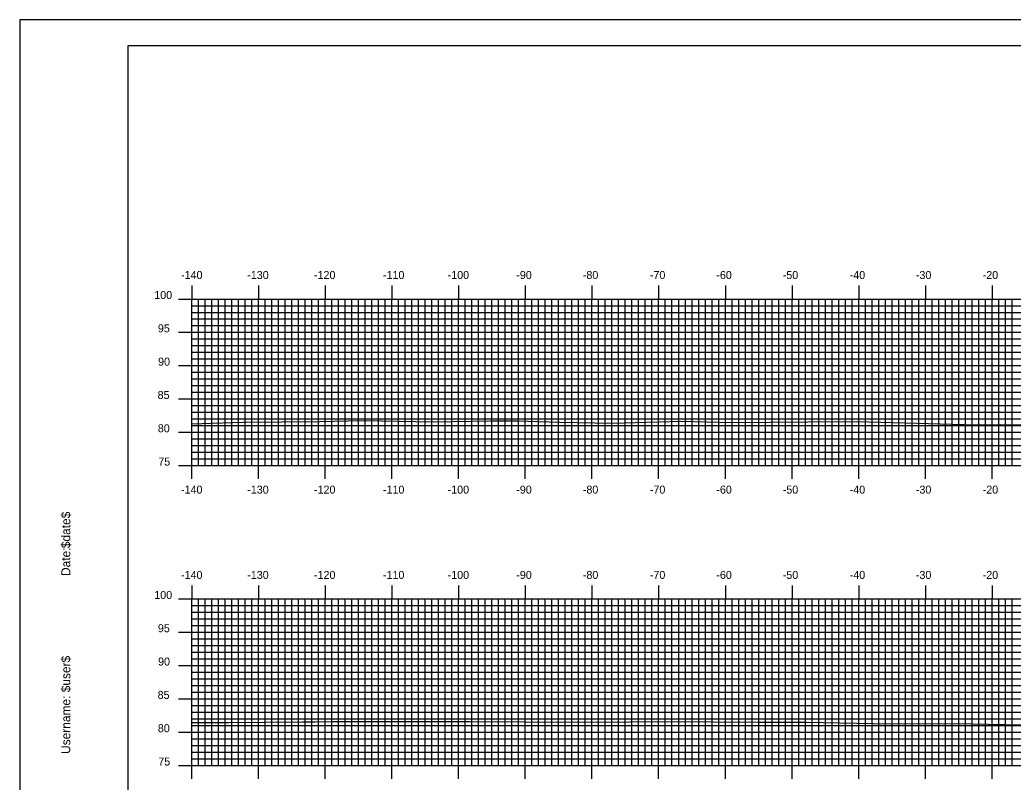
# Model space of a CAD drawing. Extents: x 856323 to 856666, y 364765 to 364985.
# Drawn here: x 856323 to 856471.9, y 364870.8 to 364985.2 of the extents above; entities that cross this region are included whole.
import ezdxf

# ---------------------------------------------------------------- set-up
doc = ezdxf.new("R2010")
doc.units = 0
for name, color, linetype in [('BORDER', 7, 'Continuous'), ('H_V ANNOTATION', 7, 'Continuous'), ('MAJOR', 7, 'Continuous'), ('MINOR', 7, 'Continuous'), ('PLOT BOUNDARY', 7, 'Continuous'), ('S_Roadway_Centerline', 7, 'Continuous')]:
    doc.layers.add(name, color=color, linetype=linetype)

msp = doc.modelspace()

# ---------------------------------------------------------------- linework, layer by layer
at = {"layer": 'BORDER'}
msp.add_lwpolyline([(856339.17, 364771.3), (856659.17, 364771.3), (856659.17, 364981.3), (856339.17, 364981.3)], close=True, dxfattribs=at)
at = {"layer": 'MAJOR'}
for p, q in [((856348.77, 364945.31), (856348.77, 364943.3)), ((856358.77, 364945.31), (856358.77, 364943.3)), ((856368.77, 364945.31), (856368.77, 364943.3)), ((856378.77, 364945.31), (856378.77, 364943.3)), ((856388.77, 364945.31), (856388.77, 364943.3)), ((856398.77, 364945.31), (856398.77, 364943.3)), ((856408.77, 364945.31), (856408.77, 364943.3)), ((856418.77, 364945.31), (856418.77, 364943.3)), ((856428.77, 364945.31), (856428.77, 364943.3)), ((856438.77, 364945.31), (856438.77, 364943.3)), ((856448.77, 364945.31), (856448.77, 364943.3)), ((856458.77, 364945.31), (856458.77, 364943.3)), ((856468.77, 364945.31), (856468.77, 364943.3)), ((856346.76, 364943.3), (856348.77, 364943.3)), ((856348.77, 364943.3), (856628.77, 364943.3)), ((856348.77, 364918.3), (856348.77, 364943.3)), ((856348.77, 364918.3), (856348.77, 364943.3)), ((856348.77, 364943.3), (856628.77, 364943.3)), ((856358.77, 364918.3), (856358.77, 364943.3)), ((856368.77, 364918.3), (856368.77, 364943.3)), ((856378.77, 364918.3), (856378.77, 364943.3)), ((856388.77, 364918.3), (856388.77, 364943.3)), ((856398.77, 364918.3), (856398.77, 364943.3)), ((856408.77, 364918.3), (856408.77, 364943.3)), ((856418.77, 364918.3), (856418.77, 364943.3)), ((856428.77, 364918.3), (856428.77, 364943.3)), ((856438.77, 364918.3), (856438.77, 364943.3)), ((856448.77, 364918.3), (856448.77, 364943.3)), ((856458.77, 364918.3), (856458.77, 364943.3)), ((856468.77, 364918.3), (856468.77, 364943.3)), ((856346.76, 364938.3), (856348.77, 364938.3)), ((856348.77, 364938.3), (856628.77, 364938.3)), ((856346.76, 364933.3), (856348.77, 364933.3)), ((856348.77, 364933.3), (856628.77, 364933.3)), ((856346.76, 364928.3), (856348.77, 364928.3)), ((856348.77, 364928.3), (856628.77, 364928.3)), ((856346.76, 364923.3), (856348.77, 364923.3)), ((856348.77, 364923.3), (856628.77, 364923.3)), ((856346.76, 364918.3), (856348.77, 364918.3)), ((856348.77, 364918.3), (856628.77, 364918.3)), ((856348.77, 364918.3), (856628.77, 364918.3)), ((856348.77, 364916.3), (856348.77, 364918.3)), ((856358.77, 364916.3), (856358.77, 364918.3)), ((856368.77, 364916.3), (856368.77, 364918.3)), ((856378.77, 364916.3), (856378.77, 364918.3)), ((856388.77, 364916.3), (856388.77, 364918.3)), ((856398.77, 364916.3), (856398.77, 364918.3)), ((856408.77, 364916.3), (856408.77, 364918.3)), ((856418.77, 364916.3), (856418.77, 364918.3)), ((856428.77, 364916.3), (856428.77, 364918.3)), ((856438.77, 364916.3), (856438.77, 364918.3)), ((856448.77, 364916.3), (856448.77, 364918.3)), ((856458.77, 364916.3), (856458.77, 364918.3)), ((856468.77, 364916.3), (856468.77, 364918.3)), ((856348.77, 364900.31), (856348.77, 364898.3)), ((856358.77, 364900.31), (856358.77, 364898.3)), ((856368.77, 364900.31), (856368.77, 364898.3)), ((856378.77, 364900.31), (856378.77, 364898.3)), ((856388.77, 364900.31), (856388.77, 364898.3)), ((856398.77, 364900.31), (856398.77, 364898.3)), ((856408.77, 364900.31), (856408.77, 364898.3)), ((856418.77, 364900.31), (856418.77, 364898.3)), ((856428.77, 364900.31), (856428.77, 364898.3)), ((856438.77, 364900.31), (856438.77, 364898.3)), ((856448.77, 364900.31), (856448.77, 364898.3)), ((856458.77, 364900.31), (856458.77, 364898.3)), ((856468.77, 364900.31), (856468.77, 364898.3)), ((856346.76, 364898.3), (856348.77, 364898.3)), ((856348.77, 364898.3), (856628.77, 364898.3)), ((856348.77, 364873.3), (856348.77, 364898.3)), ((856348.77, 364873.3), (856348.77, 364898.3)), ((856348.77, 364898.3), (856628.77, 364898.3)), ((856358.77, 364873.3), (856358.77, 364898.3)), ((856368.77, 364873.3), (856368.77, 364898.3)), ((856378.77, 364873.3), (856378.77, 364898.3)), ((856388.77, 364873.3), (856388.77, 364898.3)), ((856398.77, 364873.3), (856398.77, 364898.3)), ((856408.77, 364873.3), (856408.77, 364898.3)), ((856418.77, 364873.3), (856418.77, 364898.3)), ((856428.77, 364873.3), (856428.77, 364898.3)), ((856438.77, 364873.3), (856438.77, 364898.3)), ((856448.77, 364873.3), (856448.77, 364898.3)), ((856458.77, 364873.3), (856458.77, 364898.3)), ((856468.77, 364873.3), (856468.77, 364898.3)), ((856346.76, 364893.3), (856348.77, 364893.3)), ((856348.77, 364893.3), (856628.77, 364893.3)), ((856346.76, 364888.3), (856348.77, 364888.3)), ((856348.77, 364888.3), (856628.77, 364888.3)), ((856346.76, 364883.3), (856348.77, 364883.3)), ((856348.77, 364883.3), (856628.77, 364883.3)), ((856346.76, 364878.3), (856348.77, 364878.3)), ((856348.77, 364878.3), (856628.77, 364878.3)), ((856346.76, 364873.3), (856348.77, 364873.3)), ((856348.77, 364873.3), (856628.77, 364873.3)), ((856348.77, 364873.3), (856628.77, 364873.3)), ((856348.77, 364871.3), (856348.77, 364873.3)), ((856358.77, 364871.3), (856358.77, 364873.3)), ((856368.77, 364871.3), (856368.77, 364873.3)), ((856378.77, 364871.3), (856378.77, 364873.3)), ((856388.77, 364871.3), (856388.77, 364873.3)), ((856398.77, 364871.3), (856398.77, 364873.3)), ((856408.77, 364871.3), (856408.77, 364873.3)), ((856418.77, 364871.3), (856418.77, 364873.3)), ((856428.77, 364871.3), (856428.77, 364873.3)), ((856438.77, 364871.3), (856438.77, 364873.3)), ((856448.77, 364871.3), (856448.77, 364873.3)), ((856458.77, 364871.3), (856458.77, 364873.3)), ((856468.77, 364871.3), (856468.77, 364873.3))]:
    msp.add_line(p, q, dxfattribs=at)
at = {"layer": 'MINOR'}
for p, q in [((856349.77, 364918.3), (856349.77, 364943.3)), ((856350.77, 364918.3), (856350.77, 364943.3)), ((856351.77, 364918.3), (856351.77, 364943.3)), ((856352.77, 364918.3), (856352.77, 364943.3)), ((856353.77, 364918.3), (856353.77, 364943.3)), ((856354.77, 364918.3), (856354.77, 364943.3)), ((856355.77, 364918.3), (856355.77, 364943.3)), ((856356.77, 364918.3), (856356.77, 364943.3)), ((856357.77, 364918.3), (856357.77, 364943.3)), ((856359.77, 364918.3), (856359.77, 364943.3)), ((856360.77, 364918.3), (856360.77, 364943.3)), ((856361.77, 364918.3), (856361.77, 364943.3)), ((856362.77, 364918.3), (856362.77, 364943.3)), ((856363.77, 364918.3), (856363.77, 364943.3)), ((856364.77, 364918.3), (856364.77, 364943.3)), ((856365.77, 364918.3), (856365.77, 364943.3)), ((856366.77, 364918.3), (856366.77, 364943.3)), ((856367.77, 364918.3), (856367.77, 364943.3)), ((856369.77, 364918.3), (856369.77, 364943.3)), ((856370.77, 364918.3), (856370.77, 364943.3)), ((856371.77, 364918.3), (856371.77, 364943.3)), ((856372.77, 364918.3), (856372.77, 364943.3)), ((856373.77, 364918.3), (856373.77, 364943.3)), ((856374.77, 364918.3), (856374.77, 364943.3)), ((856375.77, 364918.3), (856375.77, 364943.3)), ((856376.77, 364918.3), (856376.77, 364943.3)), ((856377.77, 364918.3), (856377.77, 364943.3)), ((856379.77, 364918.3), (856379.77, 364943.3)), ((856380.77, 364918.3), (856380.77, 364943.3)), ((856381.77, 364918.3), (856381.77, 364943.3)), ((856382.77, 364918.3), (856382.77, 364943.3)), ((856383.77, 364918.3), (856383.77, 364943.3)), ((856384.77, 364918.3), (856384.77, 364943.3)), ((856385.77, 364918.3), (856385.77, 364943.3)), ((856386.77, 364918.3), (856386.77, 364943.3)), ((856387.77, 364918.3), (856387.77, 364943.3)), ((856389.77, 364918.3), (856389.77, 364943.3)), ((856390.77, 364918.3), (856390.77, 364943.3)), ((856391.77, 364918.3), (856391.77, 364943.3)), ((856392.77, 364918.3), (856392.77, 364943.3)), ((856393.77, 364918.3), (856393.77, 364943.3)), ((856394.77, 364918.3), (856394.77, 364943.3)), ((856395.77, 364918.3), (856395.77, 364943.3)), ((856396.77, 364918.3), (856396.77, 364943.3)), ((856397.77, 364918.3), (856397.77, 364943.3)), ((856399.77, 364918.3), (856399.77, 364943.3)), ((856400.77, 364918.3), (856400.77, 364943.3)), ((856401.77, 364918.3), (856401.77, 364943.3)), ((856402.77, 364918.3), (856402.77, 364943.3)), ((856403.77, 364918.3), (856403.77, 364943.3)), ((856404.77, 364918.3), (856404.77, 364943.3)), ((856405.77, 364918.3), (856405.77, 364943.3)), ((856406.77, 364918.3), (856406.77, 364943.3)), ((856407.77, 364918.3), (856407.77, 364943.3)), ((856409.77, 364918.3), (856409.77, 364943.3)), ((856410.77, 364918.3), (856410.77, 364943.3)), ((856411.77, 364918.3), (856411.77, 364943.3)), ((856412.77, 364918.3), (856412.77, 364943.3)), ((856413.77, 364918.3), (856413.77, 364943.3)), ((856414.77, 364918.3), (856414.77, 364943.3)), ((856415.77, 364918.3), (856415.77, 364943.3)), ((856416.77, 364918.3), (856416.77, 364943.3)), ((856417.77, 364918.3), (856417.77, 364943.3)), ((856419.77, 364918.3), (856419.77, 364943.3)), ((856420.77, 364918.3), (856420.77, 364943.3)), ((856421.77, 364918.3), (856421.77, 364943.3)), ((856422.77, 364918.3), (856422.77, 364943.3)), ((856423.77, 364918.3), (856423.77, 364943.3)), ((856424.77, 364918.3), (856424.77, 364943.3)), ((856425.77, 364918.3), (856425.77, 364943.3)), ((856426.77, 364918.3), (856426.77, 364943.3)), ((856427.77, 364918.3), (856427.77, 364943.3)), ((856429.77, 364918.3), (856429.77, 364943.3)), ((856430.77, 364918.3), (856430.77, 364943.3)), ((856431.77, 364918.3), (856431.77, 364943.3)), ((856432.77, 364918.3), (856432.77, 364943.3)), ((856433.77, 364918.3), (856433.77, 364943.3)), ((856434.77, 364918.3), (856434.77, 364943.3)), ((856435.77, 364918.3), (856435.77, 364943.3)), ((856436.77, 364918.3), (856436.77, 364943.3)), ((856437.77, 364918.3), (856437.77, 364943.3)), ((856439.77, 364918.3), (856439.77, 364943.3)), ((856440.77, 364918.3), (856440.77, 364943.3)), ((856441.77, 364918.3), (856441.77, 364943.3)), ((856442.77, 364918.3), (856442.77, 364943.3)), ((856443.77, 364918.3), (856443.77, 364943.3)), ((856444.77, 364918.3), (856444.77, 364943.3)), ((856445.77, 364918.3), (856445.77, 364943.3)), ((856446.77, 364918.3), (856446.77, 364943.3)), ((856447.77, 364918.3), (856447.77, 364943.3)), ((856449.77, 364918.3), (856449.77, 364943.3)), ((856450.77, 364918.3), (856450.77, 364943.3)), ((856451.77, 364918.3), (856451.77, 364943.3)), ((856452.77, 364918.3), (856452.77, 364943.3)), ((856453.77, 364918.3), (856453.77, 364943.3)), ((856454.77, 364918.3), (856454.77, 364943.3)), ((856455.77, 364918.3), (856455.77, 364943.3)), ((856456.77, 364918.3), (856456.77, 364943.3)), ((856457.77, 364918.3), (856457.77, 364943.3)), ((856459.77, 364918.3), (856459.77, 364943.3)), ((856460.77, 364918.3), (856460.77, 364943.3)), ((856461.77, 364918.3), (856461.77, 364943.3)), ((856462.77, 364918.3), (856462.77, 364943.3)), ((856463.77, 364918.3), (856463.77, 364943.3)), ((856464.77, 364918.3), (856464.77, 364943.3)), ((856465.77, 364918.3), (856465.77, 364943.3)), ((856466.77, 364918.3), (856466.77, 364943.3)), ((856467.77, 364918.3), (856467.77, 364943.3)), ((856469.77, 364918.3), (856469.77, 364943.3)), ((856470.77, 364918.3), (856470.77, 364943.3)), ((856471.77, 364918.3), (856471.77, 364943.3)), ((856348.77, 364942.3), (856628.77, 364942.3)), ((856348.77, 364942.3), (856350.77, 364942.3)), ((856348.77, 364941.3), (856628.77, 364941.3)), ((856348.77, 364941.3), (856350.77, 364941.3)), ((856348.77, 364940.3), (856628.77, 364940.3)), ((856348.77, 364940.3), (856350.77, 364940.3)), ((856348.77, 364939.3), (856628.77, 364939.3)), ((856348.77, 364939.3), (856350.77, 364939.3)), ((856348.77, 364937.3), (856628.77, 364937.3)), ((856348.77, 364937.3), (856350.77, 364937.3)), ((856348.77, 364936.3), (856628.77, 364936.3)), ((856348.77, 364936.3), (856350.77, 364936.3)), ((856348.77, 364935.3), (856628.77, 364935.3)), ((856348.77, 364935.3), (856350.77, 364935.3)), ((856348.77, 364934.3), (856628.77, 364934.3)), ((856348.77, 364934.3), (856350.77, 364934.3)), ((856348.77, 364932.3), (856628.77, 364932.3)), ((856348.77, 364932.3), (856350.77, 364932.3)), ((856348.77, 364931.3), (856628.77, 364931.3)), ((856348.77, 364931.3), (856350.77, 364931.3)), ((856348.77, 364930.3), (856628.77, 364930.3)), ((856348.77, 364930.3), (856350.77, 364930.3)), ((856348.77, 364929.3), (856628.77, 364929.3)), ((856348.77, 364929.3), (856350.77, 364929.3)), ((856348.77, 364927.3), (856628.77, 364927.3)), ((856348.77, 364927.3), (856350.77, 364927.3)), ((856348.77, 364926.3), (856628.77, 364926.3)), ((856348.77, 364926.3), (856350.77, 364926.3)), ((856348.77, 364925.3), (856628.77, 364925.3)), ((856348.77, 364925.3), (856350.77, 364925.3)), ((856348.77, 364924.3), (856628.77, 364924.3)), ((856348.77, 364924.3), (856350.77, 364924.3)), ((856348.77, 364922.3), (856628.77, 364922.3)), ((856348.77, 364922.3), (856350.77, 364922.3)), ((856348.77, 364921.3), (856628.77, 364921.3)), ((856348.77, 364921.3), (856350.77, 364921.3)), ((856348.77, 364920.3), (856628.77, 364920.3)), ((856348.77, 364920.3), (856350.77, 364920.3)), ((856348.77, 364919.3), (856628.77, 364919.3)), ((856348.77, 364919.3), (856350.77, 364919.3)), ((856349.77, 364873.3), (856349.77, 364898.3)), ((856350.77, 364873.3), (856350.77, 364898.3)), ((856351.77, 364873.3), (856351.77, 364898.3)), ((856352.77, 364873.3), (856352.77, 364898.3)), ((856353.77, 364873.3), (856353.77, 364898.3)), ((856354.77, 364873.3), (856354.77, 364898.3)), ((856355.77, 364873.3), (856355.77, 364898.3)), ((856356.77, 364873.3), (856356.77, 364898.3)), ((856357.77, 364873.3), (856357.77, 364898.3)), ((856359.77, 364873.3), (856359.77, 364898.3)), ((856360.77, 364873.3), (856360.77, 364898.3)), ((856361.77, 364873.3), (856361.77, 364898.3)), ((856362.77, 364873.3), (856362.77, 364898.3)), ((856363.77, 364873.3), (856363.77, 364898.3)), ((856364.77, 364873.3), (856364.77, 364898.3)), ((856365.77, 364873.3), (856365.77, 364898.3)), ((856366.77, 364873.3), (856366.77, 364898.3)), ((856367.77, 364873.3), (856367.77, 364898.3)), ((856369.77, 364873.3), (856369.77, 364898.3)), ((856370.77, 364873.3), (856370.77, 364898.3)), ((856371.77, 364873.3), (856371.77, 364898.3)), ((856372.77, 364873.3), (856372.77, 364898.3)), ((856373.77, 364873.3), (856373.77, 364898.3)), ((856374.77, 364873.3), (856374.77, 364898.3)), ((856375.77, 364873.3), (856375.77, 364898.3)), ((856376.77, 364873.3), (856376.77, 364898.3)), ((856377.77, 364873.3), (856377.77, 364898.3)), ((856379.77, 364873.3), (856379.77, 364898.3)), ((856380.77, 364873.3), (856380.77, 364898.3)), ((856381.77, 364873.3), (856381.77, 364898.3)), ((856382.77, 364873.3), (856382.77, 364898.3)), ((856383.77, 364873.3), (856383.77, 364898.3)), ((856384.77, 364873.3), (856384.77, 364898.3)), ((856385.77, 364873.3), (856385.77, 364898.3)), ((856386.77, 364873.3), (856386.77, 364898.3)), ((856387.77, 364873.3), (856387.77, 364898.3)), ((856389.77, 364873.3), (856389.77, 364898.3)), ((856390.77, 364873.3), (856390.77, 364898.3)), ((856391.77, 364873.3), (856391.77, 364898.3)), ((856392.77, 364873.3), (856392.77, 364898.3)), ((856393.77, 364873.3), (856393.77, 364898.3)), ((856394.77, 364873.3), (856394.77, 364898.3)), ((856395.77, 364873.3), (856395.77, 364898.3)), ((856396.77, 364873.3), (856396.77, 364898.3)), ((856397.77, 364873.3), (856397.77, 364898.3)), ((856399.77, 364873.3), (856399.77, 364898.3)), ((856400.77, 364873.3), (856400.77, 364898.3)), ((856401.77, 364873.3), (856401.77, 364898.3)), ((856402.77, 364873.3), (856402.77, 364898.3)), ((856403.77, 364873.3), (856403.77, 364898.3)), ((856404.77, 364873.3), (856404.77, 364898.3)), ((856405.77, 364873.3), (856405.77, 364898.3)), ((856406.77, 364873.3), (856406.77, 364898.3)), ((856407.77, 364873.3), (856407.77, 364898.3)), ((856409.77, 364873.3), (856409.77, 364898.3)), ((856410.77, 364873.3), (856410.77, 364898.3)), ((856411.77, 364873.3), (856411.77, 364898.3)), ((856412.77, 364873.3), (856412.77, 364898.3)), ((856413.77, 364873.3), (856413.77, 364898.3)), ((856414.77, 364873.3), (856414.77, 364898.3)), ((856415.77, 364873.3), (856415.77, 364898.3)), ((856416.77, 364873.3), (856416.77, 364898.3)), ((856417.77, 364873.3), (856417.77, 364898.3)), ((856419.77, 364873.3), (856419.77, 364898.3)), ((856420.77, 364873.3), (856420.77, 364898.3)), ((856421.77, 364873.3), (856421.77, 364898.3)), ((856422.77, 364873.3), (856422.77, 364898.3)), ((856423.77, 364873.3), (856423.77, 364898.3)), ((856424.77, 364873.3), (856424.77, 364898.3)), ((856425.77, 364873.3), (856425.77, 364898.3)), ((856426.77, 364873.3), (856426.77, 364898.3)), ((856427.77, 364873.3), (856427.77, 364898.3)), ((856429.77, 364873.3), (856429.77, 364898.3)), ((856430.77, 364873.3), (856430.77, 364898.3)), ((856431.77, 364873.3), (856431.77, 364898.3)), ((856432.77, 364873.3), (856432.77, 364898.3)), ((856433.77, 364873.3), (856433.77, 364898.3)), ((856434.77, 364873.3), (856434.77, 364898.3)), ((856435.77, 364873.3), (856435.77, 364898.3)), ((856436.77, 364873.3), (856436.77, 364898.3)), ((856437.77, 364873.3), (856437.77, 364898.3)), ((856439.77, 364873.3), (856439.77, 364898.3)), ((856440.77, 364873.3), (856440.77, 364898.3)), ((856441.77, 364873.3), (856441.77, 364898.3)), ((856442.77, 364873.3), (856442.77, 364898.3)), ((856443.77, 364873.3), (856443.77, 364898.3)), ((856444.77, 364873.3), (856444.77, 364898.3)), ((856445.77, 364873.3), (856445.77, 364898.3)), ((856446.77, 364873.3), (856446.77, 364898.3)), ((856447.77, 364873.3), (856447.77, 364898.3)), ((856449.77, 364873.3), (856449.77, 364898.3)), ((856450.77, 364873.3), (856450.77, 364898.3)), ((856451.77, 364873.3), (856451.77, 364898.3)), ((856452.77, 364873.3), (856452.77, 364898.3)), ((856453.77, 364873.3), (856453.77, 364898.3)), ((856454.77, 364873.3), (856454.77, 364898.3)), ((856455.77, 364873.3), (856455.77, 364898.3)), ((856456.77, 364873.3), (856456.77, 364898.3)), ((856457.77, 364873.3), (856457.77, 364898.3)), ((856459.77, 364873.3), (856459.77, 364898.3)), ((856460.77, 364873.3), (856460.77, 364898.3)), ((856461.77, 364873.3), (856461.77, 364898.3)), ((856462.77, 364873.3), (856462.77, 364898.3)), ((856463.77, 364873.3), (856463.77, 364898.3)), ((856464.77, 364873.3), (856464.77, 364898.3)), ((856465.77, 364873.3), (856465.77, 364898.3)), ((856466.77, 364873.3), (856466.77, 364898.3)), ((856467.77, 364873.3), (856467.77, 364898.3)), ((856469.77, 364873.3), (856469.77, 364898.3)), ((856470.77, 364873.3), (856470.77, 364898.3)), ((856471.77, 364873.3), (856471.77, 364898.3)), ((856348.77, 364897.3), (856628.77, 364897.3)), ((856348.77, 364897.3), (856350.77, 364897.3)), ((856348.77, 364896.3), (856628.77, 364896.3)), ((856348.77, 364896.3), (856350.77, 364896.3)), ((856348.77, 364895.3), (856628.77, 364895.3)), ((856348.77, 364895.3), (856350.77, 364895.3)), ((856348.77, 364894.3), (856628.77, 364894.3)), ((856348.77, 364894.3), (856350.77, 364894.3)), ((856348.77, 364892.3), (856628.77, 364892.3)), ((856348.77, 364892.3), (856350.77, 364892.3)), ((856348.77, 364891.3), (856628.77, 364891.3)), ((856348.77, 364891.3), (856350.77, 364891.3)), ((856348.77, 364890.3), (856628.77, 364890.3)), ((856348.77, 364890.3), (856350.77, 364890.3)), ((856348.77, 364889.3), (856628.77, 364889.3)), ((856348.77, 364889.3), (856350.77, 364889.3)), ((856348.77, 364887.3), (856628.77, 364887.3)), ((856348.77, 364887.3), (856350.77, 364887.3)), ((856348.77, 364886.3), (856628.77, 364886.3)), ((856348.77, 364886.3), (856350.77, 364886.3)), ((856348.77, 364885.3), (856628.77, 364885.3)), ((856348.77, 364885.3), (856350.77, 364885.3)), ((856348.77, 364884.3), (856628.77, 364884.3)), ((856348.77, 364884.3), (856350.77, 364884.3)), ((856348.77, 364882.3), (856628.77, 364882.3)), ((856348.77, 364882.3), (856350.77, 364882.3)), ((856348.77, 364881.3), (856628.77, 364881.3)), ((856348.77, 364881.3), (856350.77, 364881.3)), ((856348.77, 364880.3), (856628.77, 364880.3)), ((856348.77, 364880.3), (856350.77, 364880.3)), ((856348.77, 364879.3), (856628.77, 364879.3)), ((856348.77, 364879.3), (856350.77, 364879.3)), ((856348.77, 364877.3), (856628.77, 364877.3)), ((856348.77, 364877.3), (856350.77, 364877.3)), ((856348.77, 364876.3), (856628.77, 364876.3)), ((856348.77, 364876.3), (856350.77, 364876.3)), ((856348.77, 364875.3), (856628.77, 364875.3)), ((856348.77, 364875.3), (856350.77, 364875.3)), ((856348.77, 364874.3), (856628.77, 364874.3)), ((856348.77, 364874.3), (856350.77, 364874.3))]:
    msp.add_line(p, q, dxfattribs=at)
at = {"layer": 'PLOT BOUNDARY'}
msp.add_lwpolyline([(856322.98, 364765.18), (856662.98, 364765.18), (856662.98, 364985.18), (856322.98, 364985.18)], close=True, dxfattribs=at)
at = {"layer": 'S_Roadway_Centerline'}
for points in [[(856348.77, 364924.56), (856356.45, 364924.8), (856367.96, 364924.93), (856372.21, 364925.02), (856374.6, 364925.05), (856384.95, 364924.85), (856393.53, 364925.01), (856397.59, 364925.03), (856403.94, 364924.8), (856411.82, 364924.65), (856422.13, 364924.96), (856429.73, 364924.77), (856441.15, 364924.85), (856448.49, 364924.93), (856455.66, 364924.72), (856466.31, 364924.42), (856469.99, 364924.48), (856481.66, 364924.38)], [(856348.77, 364879.77), (856354.31, 364879.76), (856365.3, 364879.86), (856367.24, 364879.88), (856369.93, 364879.89), (856386.25, 364879.89), (856390.43, 364879.92), (856398.59, 364879.87), (856404.25, 364879.8), (856414.4, 364879.86), (856422.72, 364879.92), (856427.06, 364879.84), (856433.85, 364879.83), (856440.94, 364879.79), (856450.99, 364879.59), (856459.89, 364879.55), (856463.19, 364879.63), (856470.76, 364879.44), (856478.38, 364879.33)]]:
    msp.add_lwpolyline(points, dxfattribs=at)

# ---------------------------------------------------------------- texts
at = {"layer": 'BORDER'}
for s, p in [('$date$', (856330.54, 364905.91)), ('Date:', (856330.54, 364901.74)), ('$user$', (856330.54, 364884.29)), ('Username:', (856330.54, 364875.04))]:
    msp.add_text(s, height=1.339, rotation=90, dxfattribs=at).set_placement(p)
at = {"layer": 'H_V ANNOTATION'}
for s, p in [('-140', (856347.15, 364946.3)), ('-130', (856357.08, 364946.3)), ('-120', (856367.09, 364946.3)), ('-110', (856377.43, 364946.3)), ('-100', (856387.13, 364946.3)), ('-90', (856397.42, 364946.3)), ('-80', (856407.4, 364946.3)), ('-70', (856417.45, 364946.3)), ('-60', (856427.42, 364946.3)), ('-50', (856437.38, 364946.3)), ('-40', (856447.42, 364946.3)), ('-30', (856457.34, 364946.3)), ('-20', (856467.36, 364946.3)), ('100', (856343.14, 364943.3)), ('95', (856343.68, 364938.3)), ('90', (856343.71, 364933.3)), ('85', (856343.64, 364928.3)), ('80', (856343.67, 364923.3)), ('75', (856343.74, 364918.3)), ('-140', (856347.15, 364914.1)), ('-130', (856357.08, 364914.1)), ('-120', (856367.09, 364914.1)), ('-110', (856377.43, 364914.1)), ('-100', (856387.13, 364914.1)), ('-90', (856397.42, 364914.1)), ('-80', (856407.4, 364914.1)), ('-70', (856417.45, 364914.1)), ('-60', (856427.42, 364914.1)), ('-50', (856437.38, 364914.1)), ('-40', (856447.42, 364914.1)), ('-30', (856457.34, 364914.1)), ('-20', (856467.36, 364914.1)), ('-140', (856347.15, 364901.3)), ('-130', (856357.08, 364901.3)), ('-120', (856367.09, 364901.3)), ('-110', (856377.43, 364901.3)), ('-100', (856387.13, 364901.3)), ('-90', (856397.42, 364901.3)), ('-80', (856407.4, 364901.3)), ('-70', (856417.45, 364901.3)), ('-60', (856427.42, 364901.3)), ('-50', (856437.38, 364901.3)), ('-40', (856447.42, 364901.3)), ('-30', (856457.34, 364901.3)), ('-20', (856467.36, 364901.3)), ('100', (856343.14, 364898.3)), ('95', (856343.68, 364893.3)), ('90', (856343.71, 364888.3)), ('85', (856343.64, 364883.3)), ('80', (856343.67, 364878.3)), ('75', (856343.74, 364873.3))]:
    msp.add_text(s, height=1.2, dxfattribs=at).set_placement(p)
at = {"layer": 'MAJOR'}
for p in [(856348.76, 364918.3), (856348.76, 364873.3)]:
    msp.add_text('-', height=0.012, dxfattribs=at).set_placement(p)

doc.saveas('drawing.dxf')
